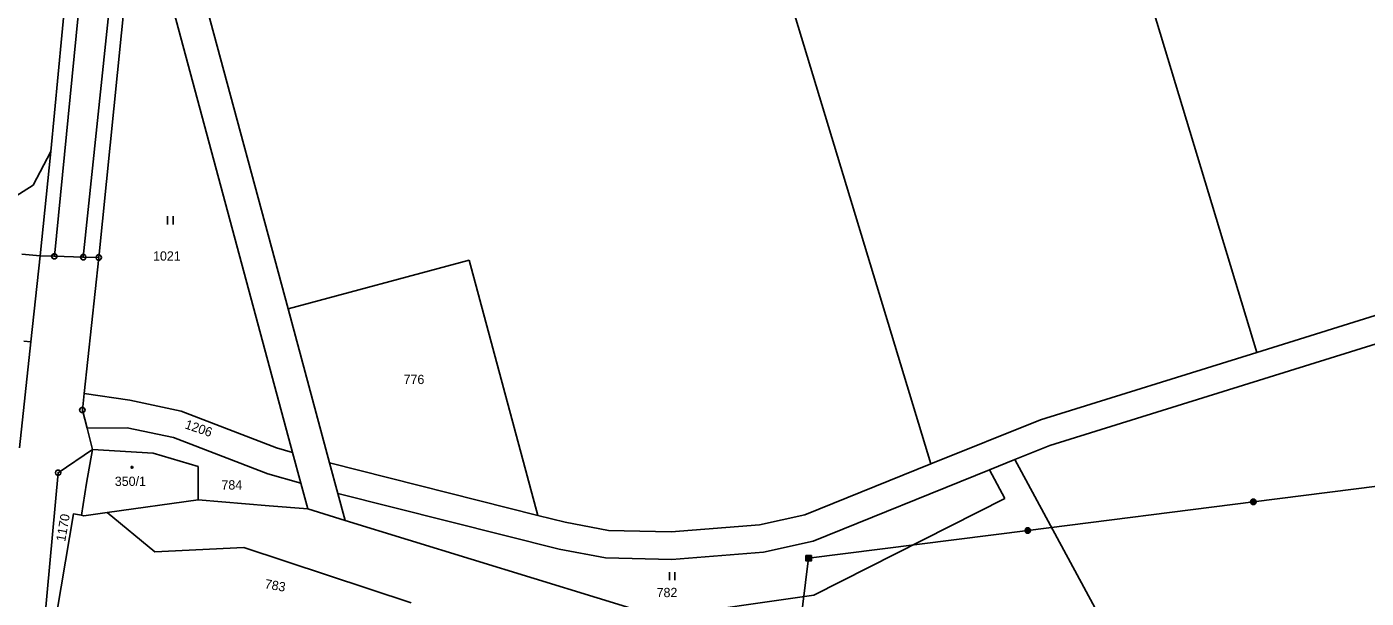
# Model space of a CAD drawing. Extents: x -812394 to -807601, y -1013098 to -1009266.
# Drawn here: x -811005.4 to -810760.5, y -1011227.4 to -1011122.9 of the extents above; entities that cross this region are included whole.
import ezdxf

# ---------------------------------------------------------------- set-up
doc = ezdxf.new("R2010")
doc.units = 0
for name, color, linetype in [('KN_HRANICE', 7, 'Continuous'), ('KN_KULTURY', 7, 'Continuous'), ('KN_MEZNIKY', 7, 'Continuous'), ('KN_PARCELY', 7, 'Continuous'), ('KN_SLUCKY', 7, 'Continuous'), ('KN_VEDENI', 7, 'Continuous')]:
    doc.layers.add(name, color=color, linetype=linetype)

# ---------------------------------------------------------------- blocks, each defined once
blk = doc.blocks.new('306')
for p, q in [((-0.5, 1.5), (-0.5, 0)), ((0.5, 0), (0.5, 1.5))]:
    blk.add_line(p, q)
blk = doc.blocks.new('NAHRADNI_SYMBOL')
blk.add_lwpolyline([(0.09, 0.15), (0.18, 0), (0.09, -0.15), (-0.09, -0.15), (-0.18, 0), (-0.09, 0.15), (0.09, 0.15)])
blk = doc.blocks.new('105')
blk.add_line((-0.12, 0), (0.12, 0))
blk.add_lwpolyline([(0.15, 0.48), (0.4, 0.3), (0.5, 0.01), (0.4, -0.28), (0.15, -0.46), (-0.16, -0.46), (-0.41, -0.28), (-0.51, 0.01), (-0.41, 0.3), (-0.16, 0.48), (0.15, 0.48)])
blk = doc.blocks.new('601')
blk.add_lwpolyline([(-0.15, 0.48), (0.16, 0.48), (0.41, 0.3), (0.51, 0.01), (0.41, -0.28), (0.16, -0.46), (-0.15, -0.46), (-0.4, -0.28), (-0.5, 0.01), (-0.4, 0.3), (-0.15, 0.48), (-0.12, 0.44), (0.12, 0.44), (0.28, 0.36), (-0.28, 0.36), (-0.36, 0.28), (0.36, 0.28), (0.36, 0.2), (-0.36, 0.2), (-0.4, 0.12), (0.4, 0.12), (0.44, 0.04), (-0.44, 0.04), (-0.44, -0.04), (0.44, -0.04), (0.41, -0.12), (-0.4, -0.12), (-0.39, -0.2), (0.42, -0.2), (0.37, -0.28), (-0.35, -0.28), (-0.27, -0.36), (0.29, -0.36), (0.18, -0.44), (-0.16, -0.44)])
blk = doc.blocks.new('602')
blk.add_lwpolyline([(-0.5, 0.5), (0.5, 0.5), (0.5, -0.5), (-0.5, -0.5), (-0.5, 0.5), (-0.44, 0.44), (0.44, 0.44), (0.44, 0.36), (-0.44, 0.36), (-0.44, 0.28), (0.44, 0.28), (0.44, 0.2), (-0.44, 0.2), (-0.44, 0.12), (0.44, 0.12), (0.44, 0.04), (-0.44, 0.04), (-0.44, -0.04), (0.44, -0.04), (0.44, -0.12), (-0.44, -0.12), (-0.44, -0.2), (0.44, -0.2), (0.44, -0.28), (-0.44, -0.28), (-0.44, -0.36), (0.44, -0.36), (0.44, -0.44), (-0.44, -0.44)])

msp = doc.modelspace()

# ---------------------------------------------------------------- linework, layer by layer
at = {"layer": 'KN_HRANICE'}
for p, q in [((-810817.55, -1011059.91), (-810780.44, -1011182.42)), ((-810840.09, -1011202.83), (-810877.77, -1011078.41)), ((-810982.45, -1011105.41), (-810956.76, -1011200.71)), ((-810957.61, -1011174.47), (-810974.27, -1011112.67)), ((-810998.22, -1011116.9), (-811000.96, -1011145.71)), ((-810590.61, -1011123.35), (-810780.44, -1011182.42)), ((-811000.96, -1011145.71), (-811004.2, -1011151.86)), ((-811002.95, -1011164.79), (-811000.96, -1011145.71)), ((-811004.2, -1011151.86), (-811011.7, -1011156.55)), ((-811002.95, -1011164.79), (-811006.28, -1011164.5)), ((-811004.64, -1011180.47), (-811002.95, -1011164.79)), ((-811000.33, -1011164.87), (-811002.95, -1011164.79)), ((-810995.05, -1011165.02), (-811000.33, -1011164.87)), ((-810992.21, -1011165.1), (-810995.05, -1011165.02)), ((-810994.88, -1011189.95), (-810992.21, -1011165.1)), ((-810957.61, -1011174.47), (-810924.51, -1011165.55)), ((-810924.51, -1011165.55), (-810911.92, -1011212.23)), ((-810950.02, -1011202.64), (-810957.61, -1011174.47)), ((-810818.33, -1011199.44), (-810741.21, -1011175.44)), ((-811006.73, -1011199.88), (-811004.64, -1011180.47)), ((-811005.89, -1011180.37), (-811004.64, -1011180.47)), ((-810780.44, -1011182.42), (-810820.01, -1011194.73)), ((-810995.21, -1011192.97), (-810994.88, -1011189.95)), ((-810986.52, -1011191.18), (-810994.88, -1011189.95)), ((-810994.36, -1011196.29), (-810995.21, -1011192.97)), ((-810977.14, -1011193.18), (-810986.52, -1011191.18)), ((-810959.71, -1011199.86), (-810977.14, -1011193.18)), ((-810820.01, -1011194.73), (-810840.09, -1011202.83)), ((-810994.36, -1011196.29), (-810987, -1011196.19)), ((-810993.37, -1011200.18), (-810994.36, -1011196.29)), ((-810987, -1011196.19), (-810978.56, -1011197.99)), ((-810978.56, -1011197.99), (-810961.3, -1011204.6)), ((-810999.64, -1011204.43), (-810993.37, -1011200.18)), ((-810982.24, -1011200.82), (-810993.37, -1011200.18)), ((-810956.76, -1011200.71), (-810959.71, -1011199.86)), ((-810824.69, -1011202.01), (-810818.33, -1011199.44)), ((-810974.04, -1011203.29), (-810982.24, -1011200.82)), ((-810955.24, -1011206.35), (-810956.76, -1011200.71)), ((-810950.02, -1011202.64), (-810948.51, -1011208.24)), ((-810911.92, -1011212.23), (-810950.02, -1011202.64)), ((-810840.09, -1011202.83), (-810863.09, -1011212.12)), ((-810829.36, -1011203.9), (-810824.69, -1011202.01)), ((-810806.75, -1011235.18), (-810824.69, -1011202.01)), ((-811002.17, -1011232.3), (-810999.64, -1011204.43)), ((-810974.02, -1011209.41), (-810974.04, -1011203.29)), ((-810961.3, -1011204.6), (-810955.24, -1011206.35)), ((-810861.6, -1011216.92), (-810829.36, -1011203.9)), ((-810829.36, -1011203.9), (-810826.53, -1011209.12)), ((-810953.98, -1011211.02), (-810955.24, -1011206.35)), ((-810990.68, -1011211.7), (-810974.02, -1011209.41)), ((-810961.08, -1011210.45), (-810974.02, -1011209.41)), ((-810947.19, -1011213.16), (-810948.51, -1011208.24)), ((-810948.51, -1011208.24), (-810908.01, -1011218.37)), ((-810826.53, -1011209.12), (-810861.45, -1011226.78)), ((-810995.36, -1011212.19), (-810994.94, -1011212.29)), ((-810994.94, -1011212.29), (-810990.68, -1011211.7)), ((-810990.68, -1011211.7), (-810981.95, -1011218.9)), ((-810953.98, -1011211.02), (-810961.08, -1011210.45)), ((-810947.19, -1011213.16), (-810953.98, -1011211.02)), ((-810906.93, -1011213.49), (-810911.92, -1011212.23)), ((-810863.09, -1011212.12), (-810871.4, -1011213.98)), ((-810889.59, -1011230.84), (-810947.19, -1011213.16)), ((-810899, -1011215.01), (-810906.93, -1011213.49)), ((-810887.58, -1011215.26), (-810899, -1011215.01)), ((-810871.4, -1011213.98), (-810887.58, -1011215.26)), ((-810870.66, -1011218.94), (-810861.6, -1011216.92)), ((-810981.95, -1011218.9), (-810965.7, -1011218.1)), ((-810965.7, -1011218.1), (-810935.11, -1011228.19)), ((-810908.01, -1011218.37), (-810899.53, -1011220)), ((-810899.53, -1011220), (-810887.44, -1011220.26)), ((-810887.44, -1011220.26), (-810870.66, -1011218.94)), ((-810861.45, -1011226.78), (-810889.59, -1011230.84))]:
    msp.add_line(p, q, dxfattribs=at)
for points in [[(-810986.65, -1011105.04), (-810987.39, -1011117.32), (-810992.21, -1011165.1)], [(-810993.37, -1011200.18), (-810994.44, -1011206.32), (-810995.36, -1011212.19)], [(-811000.55, -1011233.96), (-810996.85, -1011211.94), (-810995.36, -1011212.19)]]:
    msp.add_lwpolyline(points, dxfattribs=at)
at = {"layer": 'KN_SLUCKY'}
for points in [[(-811000.33, -1011164.87), (-810995.6, -1011117.04), (-810993.22, -1011089.39), (-810991.44, -1011051.79), (-810989.93, -1011025.95), (-810988.35, -1011012.09), (-810985.51, -1010996.59), (-810982.68, -1010987.06), (-810978.95, -1010979.06), (-810975.35, -1010972.95)], [(-810970.63, -1010976.53), (-810974.13, -1010981.9), (-810977.67, -1010989.22), (-810980.74, -1010998.6), (-810983.37, -1011013.1), (-810984.59, -1011025.93), (-810986.15, -1011052.66), (-810988.17, -1011090.35), (-810990.05, -1011117.32), (-810995.05, -1011165.02)]]:
    msp.add_lwpolyline(points, dxfattribs=at)
at = {"layer": 'KN_VEDENI'}
msp.add_line((-810862.42, -1011220.06), (-810876.89, -1011337.57), dxfattribs=at)
msp.add_lwpolyline([(-809847.74, -1011090.69), (-809935.67, -1011101.99), (-810048.36, -1011116.35), (-810161.44, -1011130.66), (-810270.03, -1011144.67), (-810376.1, -1011158.31), (-810487.14, -1011172.35), (-810591.19, -1011185.57), (-810690.15, -1011198.24), (-810781.09, -1011209.76), (-810822.35, -1011215), (-810862.42, -1011220.06)], dxfattribs=at)

# ---------------------------------------------------------------- block references
at = {"layer": 'KN_KULTURY'}
for name, p in [('306', (-810979.13, -1011159.04)), ('NAHRADNI_SYMBOL', (-810986.14, -1011203.43)), ('306', (-810887.37, -1011224.08))]:
    msp.add_blockref(name, p, dxfattribs=at)
at = {"layer": 'KN_MEZNIKY'}
for p in [(-811000.33, -1011164.87), (-810995.05, -1011165.02), (-810992.21, -1011165.1), (-810995.21, -1011192.97), (-810999.64, -1011204.43)]:
    msp.add_blockref('105', p, dxfattribs=at)
at = {"layer": 'KN_VEDENI'}
for name, p in [('601', (-810781.09, -1011209.76)), ('601', (-810822.35, -1011215)), ('602', (-810862.42, -1011220.06))]:
    msp.add_blockref(name, p, dxfattribs=at)

# ---------------------------------------------------------------- texts
at = {"layer": 'KN_PARCELY'}
for s, p in [('1021', (-810982.29, -1011165.66)), ('776', (-810936.48, -1011188.22)), ('350/1', (-810989.28, -1011206.84)), ('784', (-810969.78, -1011207.5)), ('782', (-810890.21, -1011227.17))]:
    msp.add_text(s, height=1.7, dxfattribs=at).set_placement(p)
for s, rotation, p in [('1206', 341.139, (-810976.6, -1011196.29)), ('1170', 80.042, (-810998.36, -1011217.11)), ('783', 349.848, (-810961.96, -1011225.53))]:
    msp.add_text(s, height=1.7, rotation=rotation, dxfattribs=at).set_placement(p)

doc.saveas('drawing.dxf')
